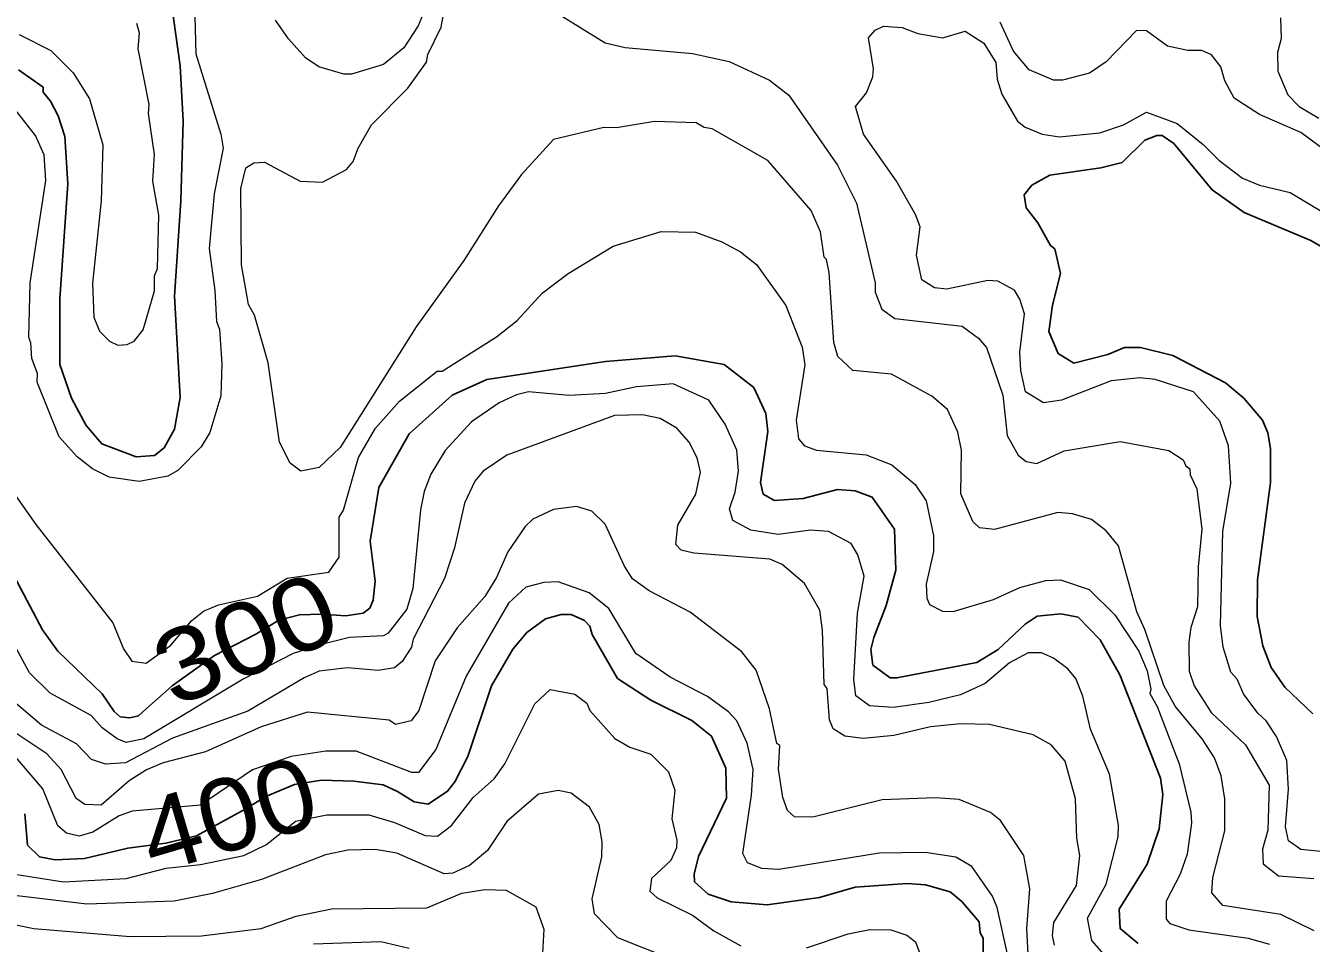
# Model space of a CAD drawing. Extents: x 673.3 to 698.5, y 6984.3 to 7012.3.
# Drawn here: x 691.219 to 692.636, y 6995.457 to 6996.468 of the extents above; entities that cross this region are included whole.
import ezdxf
from ezdxf.enums import TextEntityAlignment as Align

# ---------------------------------------------------------------- set-up
doc = ezdxf.new("R2010")
doc.units = 0
doc.header["$LTSCALE"] = 0.032
doc.layers.add('1', color=7, linetype='Continuous', lineweight=25)
doc.layers.add('2', color=7, linetype='Continuous', lineweight=13)
doc.layers.add('61', color=7, linetype='Continuous')

msp = doc.modelspace()

# ---------------------------------------------------------------- linework, layer by layer
at = {"layer": '1'}
for points in [[(691.2112, 6996.4198), (691.2385, 6996.4005), (691.2384, 6996.3951), (691.2467, 6996.3853), (691.2551, 6996.3689), (691.2625, 6996.3462), (691.2658, 6996.294), (691.2569, 6996.1674), (691.2569, 6996.095), (691.2697, 6996.0578), (691.2858, 6996.0277), (691.3031, 6996.0076), (691.3408, 6995.9932), (691.361, 6995.9947), (691.3718, 6996.0032), (691.3831, 6996.0237), (691.3895, 6996.0588), (691.3831, 6996.1705), (691.3903, 6996.2754), (691.3929, 6996.3632), (691.3895, 6996.4242), (691.3692, 6996.5689)], [(692.6373, 6995.7103), (692.6065, 6995.7395), (692.5912, 6995.7611), (692.5823, 6995.7852), (692.5757, 6995.8174), (692.5762, 6995.8579), (692.5907, 6995.965), (692.5907, 6996.0024), (692.5876, 6996.0197), (692.5818, 6996.0338), (692.5612, 6996.0578), (692.5409, 6996.0747), (692.483, 6996.1048), (692.4474, 6996.1137), (692.4296, 6996.1137), (692.4113, 6996.1062), (692.3741, 6996.0967), (692.3567, 6996.1071), (692.3465, 6996.1316), (692.3506, 6996.1604), (692.3594, 6996.1952), (692.353, 6996.2225), (692.3482, 6996.2261), (692.3344, 6996.2511), (692.3213, 6996.2677), (692.3191, 6996.2819), (692.3278, 6996.2928), (692.3475, 6996.3035), (692.4037, 6996.3116), (692.427, 6996.3177), (692.4521, 6996.3423), (692.4653, 6996.3474), (692.4713, 6996.3472), (692.4839, 6996.3386), (692.5262, 6996.2874), (692.5617, 6996.2626), (692.635, 6996.2316), (692.6694, 6996.2114)], [(692.4447, 6995.457), (692.4248, 6995.4736), (692.424, 6995.495), (692.4548, 6995.5445), (692.4681, 6995.5833), (692.4718, 6995.6213), (692.4693, 6995.6392), (692.4245, 6995.7532), (692.4028, 6995.7917), (692.3787, 6995.8165), (692.3595, 6995.8205), (692.3336, 6995.8176), (692.3202, 6995.8089), (692.2905, 6995.781), (692.2671, 6995.7667), (692.1791, 6995.7497), (692.1715, 6995.75), (692.1526, 6995.7638), (692.1503, 6995.7811), (692.1537, 6995.7943), (692.1673, 6995.8294), (692.1779, 6995.8685), (692.1764, 6995.9136), (692.1519, 6995.9489), (692.1331, 6995.9557), (692.1135, 6995.9573), (692.0758, 6995.9475), (692.0441, 6995.9453), (692.0317, 6995.9522), (692.0289, 6995.9649), (692.037, 6996.0213), (692.0345, 6996.0412), (692.0213, 6996.0699), (691.9888, 6996.0952), (691.9347, 6996.1047), (691.8581, 6996.0983), (691.7272, 6996.0785), (691.6891, 6996.0611), (691.6416, 6996.0186), (691.6084, 6995.9594), (691.5989, 6995.9003), (691.6044, 6995.8563), (691.6021, 6995.8354), (691.5984, 6995.8267), (691.591, 6995.821), (691.572, 6995.8181), (691.5451, 6995.8198), (691.521, 6995.8194), (691.4982, 6995.8133), (691.4728, 6995.7979), (691.4271, 6995.7746), (691.3808, 6995.7409), (691.3521, 6995.7155), (691.3434, 6995.708), (691.3339, 6995.7057), (691.3234, 6995.7068), (691.3167, 6995.7126), (691.3035, 6995.7323), (691.2547, 6995.7792), (691.2377, 6995.8027), (691.1783, 6995.9148)], [(691.2184, 6995.6001), (691.2213, 6995.5654), (691.2344, 6995.5525), (691.2516, 6995.5494), (691.2842, 6995.5509), (691.3317, 6995.5623), (691.3737, 6995.5675), (691.4076, 6995.5758), (691.4612, 6995.6051), (691.484, 6995.6192), (691.5154, 6995.6322), (691.5451, 6995.6371), (691.5809, 6995.636), (691.613, 6995.6318), (691.6287, 6995.6246), (691.6473, 6995.6132), (691.6628, 6995.6105), (691.684, 6995.6248), (691.692, 6995.6353), (691.7062, 6995.663), (691.7323, 6995.7412), (691.7558, 6995.7813), (691.7713, 6995.7999), (691.7919, 6995.8148), (691.809, 6995.8197), (691.8203, 6995.8197), (691.835, 6995.8131), (691.8407, 6995.8066), (691.8433, 6995.7974), (691.8714, 6995.7492), (691.9078, 6995.7251), (691.953, 6995.7028), (691.9748, 6995.6857), (691.9906, 6995.6503), (691.9914, 6995.6173), (691.9606, 6995.5529), (691.9556, 6995.5334), (691.956, 6995.5252), (691.9712, 6995.5114), (691.9966, 6995.5029), (692.0361, 6995.4997), (692.0937, 6995.5078), (692.1331, 6995.5192), (692.1903, 6995.5232), (692.2106, 6995.5217), (692.2376, 6995.5141), (692.2505, 6995.5035), (692.2697, 6995.4811), (692.2708, 6995.4687), (692.2739, 6995.463), (692.274, 6995.4431)]]:
    msp.add_lwpolyline(points, dxfattribs=at)
at = {"layer": '2'}
for points in [[(692.6387, 6995.4711), (692.602, 6995.4891), (692.5382, 6995.499), (692.526, 6995.5131), (692.5272, 6995.5298), (692.5402, 6995.5813), (692.5402, 6995.6164), (692.5362, 6995.6418), (692.5288, 6995.6617), (692.5152, 6995.6827), (692.4857, 6995.7187), (692.4729, 6995.7414), (692.4522, 6995.803), (692.4434, 6995.8224), (692.4232, 6995.8952), (692.4097, 6995.9119), (692.3933, 6995.9243), (692.3723, 6995.9305), (692.3563, 6995.932), (692.2865, 6995.9134), (692.2699, 6995.915), (692.2625, 6995.9219), (692.2496, 6995.9527), (692.2503, 6996.0005), (692.246, 6996.0206), (692.2347, 6996.0454), (692.2176, 6996.0601), (692.173, 6996.0843), (692.1305, 6996.0883), (692.1138, 6996.1039), (692.1095, 6996.1194), (692.1044, 6996.1965), (692.1014, 6996.2109), (692.0989, 6996.2133), (692.0949, 6996.2413), (692.0846, 6996.2649), (692.0367, 6996.3199), (691.9756, 6996.3547), (691.9667, 6996.3562), (691.9577, 6996.3612), (691.9119, 6996.3629), (691.8702, 6996.3558), (691.856, 6996.3563), (691.8007, 6996.3431), (691.7653, 6996.3045), (691.7401, 6996.2698), (691.7021, 6996.2095), (691.6493, 6996.1365), (691.5658, 6996.0037), (691.5424, 6995.9814), (691.5225, 6995.9777), (691.5106, 6995.9862), (691.4988, 6996.0096), (691.4864, 6996.0969), (691.4715, 6996.1493), (691.4649, 6996.1612), (691.4571, 6996.2047), (691.4564, 6996.2891), (691.4617, 6996.3117), (691.4707, 6996.3173), (691.4823, 6996.318), (691.5218, 6996.2972), (691.5464, 6996.2961), (691.5725, 6996.3098), (691.58, 6996.3188), (691.5855, 6996.3333), (691.6003, 6996.359), (691.6402, 6996.3996), (691.6607, 6996.4283), (691.6623, 6996.4367), (691.6771, 6996.4666), (691.6867, 6996.5211)], [(691.405, 6996.5073), (691.4067, 6996.4373), (691.4344, 6996.3488), (691.4367, 6996.3333), (691.4269, 6996.283), (691.4214, 6996.223), (691.4278, 6996.1767), (691.4295, 6996.1423), (691.4327, 6996.134), (691.4352, 6996.0959), (691.4343, 6996.0607), (691.4221, 6996.02), (691.4127, 6996.0042), (691.3869, 6995.9783)], [(691.6591, 6996.4858), (691.6518, 6996.4683), (691.6359, 6996.4439), (691.6135, 6996.4255), (691.5783, 6996.4151), (691.5696, 6996.415), (691.5423, 6996.423), (691.5274, 6996.4328), (691.5088, 6996.4538), (691.4946, 6996.4744)], [(691.7893, 6996.4918), (691.8578, 6996.4493), (691.8795, 6996.4445), (691.9537, 6996.4378), (691.9944, 6996.4289), (692.0386, 6996.4084), (692.0601, 6996.3918), (692.1137, 6996.3146), (692.1346, 6996.2728), (692.1549, 6996.1851), (692.1551, 6996.1747), (692.1624, 6996.1561), (692.1769, 6996.1457), (692.2509, 6996.1372), (692.269, 6996.1242), (692.2778, 6996.1139), (692.2958, 6996.0613), (692.3004, 6996.0168), (692.3127, 6995.9952), (692.3215, 6995.9882), (692.3333, 6995.986), (692.3633, 6995.9998), (692.4251, 6996.0102), (692.4784, 6996.0004), (692.4943, 6995.9902), (692.4973, 6995.9834), (692.5017, 6995.9802), (692.5021, 6995.9734), (692.5093, 6995.9581), (692.515, 6995.9135), (692.511, 6995.8721), (692.5101, 6995.8279), (692.5029, 6995.8053), (692.5007, 6995.7893), (692.5011, 6995.7572), (692.5063, 6995.741), (692.5253, 6995.7118), (692.5632, 6995.6761), (692.589, 6995.6317), (692.5875, 6995.5819), (692.5819, 6995.561), (692.5826, 6995.5449), (692.5992, 6995.5315), (692.6383, 6995.5289)], [(691.2121, 6996.4586), (691.2468, 6996.4412), (691.2716, 6996.4164), (691.2896, 6996.3876), (691.3041, 6996.337), (691.3024, 6996.2755), (691.2927, 6996.1848), (691.2942, 6996.1474), (691.3006, 6996.1319), (691.3116, 6996.1209), (691.3207, 6996.1162), (691.3312, 6996.1172), (691.3388, 6996.1209), (691.3488, 6996.1333), (691.361, 6996.1764), (691.3611, 6996.1927), (691.3643, 6996.2009), (691.3659, 6996.2597), (691.3595, 6996.2969), (691.361, 6996.3265), (691.3546, 6996.3716), (691.3553, 6996.3816), (691.3432, 6996.4429), (691.3447, 6996.4603), (691.3416, 6996.4707)], [(692.6646, 6995.5565), (692.6239, 6995.5606), (692.6103, 6995.5701), (692.607, 6995.5855), (692.6104, 6995.627), (692.6086, 6995.6589), (692.597, 6995.6853), (692.5859, 6995.7024), (692.5765, 6995.711), (692.561, 6995.7321), (692.5538, 6995.7484), (692.547, 6995.7562), (692.5386, 6995.7838), (692.5354, 6995.8074), (692.5379, 6995.9112), (692.5467, 6995.9644), (692.5443, 6996.0054), (692.5349, 6996.0325), (692.5059, 6996.0648), (692.4635, 6996.0787), (692.4468, 6996.0803), (692.4149, 6996.077), (692.3602, 6996.0556), (692.3405, 6996.0527), (692.3205, 6996.065), (692.3156, 6996.0885), (692.3146, 6996.1086), (692.3195, 6996.1508), (692.3145, 6996.1669), (692.3084, 6996.1769), (692.2902, 6996.187), (692.2791, 6996.1877), (692.2339, 6996.1781), (692.2205, 6996.1797), (692.2066, 6996.1885), (692.2006, 6996.2154), (692.2046, 6996.2466), (692.1994, 6996.2602), (692.1786, 6996.2969), (692.1422, 6996.3488), (692.1333, 6996.3792), (692.1455, 6996.3944), (692.1525, 6996.412), (692.1533, 6996.4209), (692.1479, 6996.4549), (692.155, 6996.4636), (692.1643, 6996.4679), (692.1849, 6996.4664), (692.2021, 6996.4596), (692.2296, 6996.455), (692.2542, 6996.4622), (692.2747, 6996.4491), (692.288, 6996.4277), (692.2895, 6996.4093), (692.2945, 6996.3928), (692.3118, 6996.363), (692.3202, 6996.3565), (692.3389, 6996.3489), (692.3581, 6996.3459), (692.4025, 6996.3504), (692.4285, 6996.3591), (692.4541, 6996.3732), (692.4876, 6996.3607), (692.5165, 6996.3376), (692.5335, 6996.3201), (692.5596, 6996.3003), (692.5783, 6996.2927), (692.6122, 6996.2845), (692.6638, 6996.2539)], [(692.3514, 6996.4085), (692.3246, 6996.4198), (692.3074, 6996.4402), (692.2928, 6996.4722)], [(692.6014, 6996.4771), (692.6022, 6996.4543), (692.5981, 6996.4389), (692.5988, 6996.4184), (692.6096, 6996.3922), (692.6222, 6996.3794), (692.6439, 6996.3665)], [(692.6888, 6996.3024), (692.624, 6996.3507), (692.5784, 6996.3707), (692.5505, 6996.3886), (692.5403, 6996.4077), (692.536, 6996.4232), (692.5255, 6996.4361), (692.515, 6996.441), (692.4996, 6996.4411), (692.4771, 6996.4459), (692.4541, 6996.4628), (692.4429, 6996.463), (692.4094, 6996.4284), (692.391, 6996.4161), (692.3614, 6996.4085), (692.3514, 6996.4085)], [(691.3869, 6995.9783), (691.3757, 6995.972), (691.3444, 6995.9662), (691.3111, 6995.971), (691.2929, 6995.98), (691.2761, 6995.9933), (691.2561, 6996.0153), (691.2319, 6996.0756), (691.2322, 6996.0851), (691.2259, 6996.1016), (691.2251, 6996.1188), (691.2226, 6996.1247), (691.2243, 6996.1851), (691.2413, 6996.2979), (691.2397, 6996.326), (691.2299, 6996.3474), (691.2036, 6996.3811)], [(691.171, 6996.0027), (691.2303, 6995.9187), (691.3154, 6995.8106), (691.327, 6995.7817), (691.3361, 6995.7682), (691.3521, 6995.766), (691.3793, 6995.7858), (691.4023, 6995.8129), (691.4153, 6995.8232), (691.4317, 6995.8304), (691.4745, 6995.8398), (691.5072, 6995.8595), (691.5534, 6995.8664), (691.5646, 6995.8827), (691.5647, 6995.9269), (691.5695, 6995.9346), (691.586, 6995.9926), (691.6047, 6996.0251), (691.6311, 6996.0547), (691.6724, 6996.0876), (691.6782, 6996.0879), (691.7378, 6996.1254), (691.7607, 6996.1437), (691.7883, 6996.1737), (691.8168, 6996.1955), (691.8666, 6996.2255), (691.9195, 6996.2415), (691.9572, 6996.2407), (691.986, 6996.2304), (692.0066, 6996.2191), (692.0243, 6996.2053), (692.0565, 6996.1601), (692.0745, 6996.1143), (692.0777, 6996.0947), (692.068, 6996.0336), (692.0707, 6996.0131), (692.0771, 6996.0054), (692.0905, 6996.0005), (692.1451, 6995.9954), (692.1733, 6995.9844), (692.1992, 6995.9628), (692.2114, 6995.9447), (692.2194, 6995.9063), (692.2194, 6995.8892), (692.2113, 6995.8529), (692.2119, 6995.8377), (692.2149, 6995.8308), (692.2292, 6995.8234), (692.2409, 6995.823), (692.2855, 6995.8363), (692.3145, 6995.8492), (692.3432, 6995.8571), (692.3594, 6995.8579), (692.3908, 6995.8471), (692.4191, 6995.8194), (692.4457, 6995.7793), (692.4546, 6995.7574), (692.4588, 6995.7375), (692.4576, 6995.7325), (692.4656, 6995.7181)], [(692.407, 6995.4455), (692.3938, 6995.4603), (692.3888, 6995.4849), (692.4097, 6995.5226), (692.4229, 6995.5748), (692.423, 6995.5874), (692.4132, 6995.6438), (692.3921, 6995.6933), (692.384, 6995.7298), (692.376, 6995.7491), (692.3674, 6995.7596), (692.3516, 6995.7715), (692.3383, 6995.7773), (692.3236, 6995.7773), (692.303, 6995.7665), (692.2761, 6995.7435), (692.249, 6995.731), (692.2143, 6995.7227), (692.1748, 6995.7171), (692.1488, 6995.7191), (692.1338, 6995.7301), (692.1314, 6995.748), (692.1355, 6995.821), (692.1428, 6995.8618), (692.1361, 6995.8852), (692.1286, 6995.898), (692.1036, 6995.9109), (692.084, 6995.9125), (692.0483, 6995.9078), (692.018, 6995.9124), (691.9981, 6995.9231), (691.9947, 6995.9359), (692.001, 6995.9543), (692.0044, 6995.9775), (692.0026, 6996.0008), (691.99, 6996.0293), (691.9718, 6996.0557), (691.9327, 6996.0737), (691.892, 6996.0705), (691.8581, 6996.0632), (691.8181, 6996.0608), (691.7731, 6996.0648), (691.7598, 6996.0616), (691.7408, 6996.0527), (691.7102, 6996.032), (691.6814, 6996.0002), (691.6655, 6995.9742), (691.6583, 6995.9552), (691.6542, 6995.935), (691.6459, 6995.8484), (691.6392, 6995.8256), (691.6187, 6995.7991), (691.6133, 6995.7961), (691.5759, 6995.7944), (691.5466, 6995.7871), (691.5141, 6995.7765), (691.4589, 6995.7483), (691.3494, 6995.6826), (691.3301, 6995.6787), (691.3199, 6995.6826), (691.3035, 6995.6946), (691.2914, 6995.7083), (691.2462, 6995.7331), (691.2234, 6995.7554), (691.2037, 6995.7922)], [(692.1418, 6995.6829), (692.1215, 6995.6855), (692.1087, 6995.6938), (692.1046, 6995.7034), (692.1021, 6995.7379), (692.0989, 6995.7426), (692.0972, 6995.8024), (692.094, 6995.8243), (692.0771, 6995.8537), (692.0527, 6995.8748), (692.0391, 6995.8807), (691.9553, 6995.8873), (691.9412, 6995.8905), (691.9355, 6995.8966), (691.9376, 6995.9179), (691.9574, 6995.9522), (691.9628, 6995.9765), (691.9588, 6995.9923), (691.95, 6996.0094), (691.9367, 6996.025), (691.9184, 6996.0354), (691.8988, 6996.0395), (691.8679, 6996.0387), (691.7493, 6995.995), (691.7231, 6995.9774), (691.7142, 6995.9665), (691.7025, 6995.9424), (691.6916, 6995.893), (691.6805, 6995.8594), (691.6463, 6995.7926), (691.6444, 6995.7838), (691.634, 6995.7679), (691.6256, 6995.7607), (691.6077, 6995.7578), (691.5738, 6995.761), (691.5427, 6995.7572), (691.5261, 6995.7499), (691.464, 6995.7131), (691.3809, 6995.6834), (691.3294, 6995.6562), (691.3071, 6995.6547), (691.2916, 6995.6598), (691.2753, 6995.6771), (691.2367, 6995.6977), (691.2046, 6995.7247)], [(692.0468, 6995.6774), (692.0386, 6995.7157), (692.0238, 6995.7581), (692.0082, 6995.7783), (691.9512, 6995.8223), (691.9062, 6995.8458), (691.8879, 6995.8589), (691.879, 6995.8727), (691.8578, 6995.919), (691.843, 6995.9333), (691.826, 6995.9386), (691.8008, 6995.9353), (691.7781, 6995.9248), (691.7696, 6995.9165), (691.7504, 6995.8888), (691.738, 6995.8602), (691.7252, 6995.8395), (691.6947, 6995.8048), (691.6703, 6995.7686), (691.6525, 6995.7139), (691.6438, 6995.7026), (691.6266, 6995.6984), (691.6197, 6995.7032), (691.5297, 6995.7121), (691.4786, 6995.6959), (691.4174, 6995.6682), (691.3709, 6995.6562), (691.3523, 6995.6483), (691.3332, 6995.6365), (691.3024, 6995.6097), (691.2846, 6995.6104), (691.2748, 6995.617), (691.2584, 6995.6487), (691.2426, 6995.6661), (691.1931, 6995.6993)], [(692.0302, 6995.5397), (692.0143, 6995.546), (692.0094, 6995.5562), (692.019, 6995.6204), (692.0206, 6995.6489), (692.0141, 6995.678), (692.0027, 6995.7023), (691.9936, 6995.7122), (691.9702, 6995.7292), (691.9293, 6995.7504), (691.8914, 6995.7766), (691.8618, 6995.8262), (691.8401, 6995.8435), (691.8057, 6995.8555), (691.79, 6995.8548), (691.7704, 6995.8498), (691.751, 6995.8321), (691.7045, 6995.7515), (691.671, 6995.6709), (691.6519, 6995.6457), (691.6445, 6995.6455), (691.5835, 6995.6691), (691.55, 6995.669), (691.5117, 6995.6633), (691.4691, 6995.6484), (691.412, 6995.6096), (691.3366, 6995.603), (691.3223, 6995.5979), (691.2934, 6995.5798), (691.2783, 6995.5754), (691.2644, 6995.5786), (691.2546, 6995.5868), (691.238, 6995.6275), (691.2019, 6995.6702)], [(691.1956, 6995.5355), (691.261, 6995.525), (691.3298, 6995.5286), (691.3741, 6995.5403), (691.412, 6995.5442), (691.4597, 6995.5539), (691.4846, 6995.5663), (691.5164, 6995.5918), (691.5509, 6995.5988), (691.5972, 6995.5989), (691.6256, 6995.5906), (691.6594, 6995.5761), (691.6729, 6995.5754), (691.6882, 6995.5873), (691.7124, 6995.618), (691.7352, 6995.6385), (691.747, 6995.6552), (691.7802, 6995.7212), (691.7971, 6995.737), (691.8242, 6995.7319), (691.8373, 6995.7219), (691.8409, 6995.7137), (691.8684, 6995.683), (691.8849, 6995.6734), (691.9081, 6995.6657), (691.9273, 6995.6464), (691.9345, 6995.626), (691.9312, 6995.5946), (691.9367, 6995.5711), (691.9362, 6995.5624), (691.93, 6995.5484), (691.9085, 6995.5289), (691.9067, 6995.5146), (691.9148, 6995.5075), (691.9539, 6995.4882), (691.9773, 6995.4709)], [(692.4656, 6995.7181), (692.4898, 6995.655), (692.5027, 6995.602), (692.5036, 6995.5898), (692.4987, 6995.5556), (692.4909, 6995.5336), (692.4756, 6995.5037), (692.4756, 6995.484), (692.4798, 6995.479), (692.5006, 6995.4721), (692.5661, 6995.463), (692.5894, 6995.4563)], [(692.3528, 6995.4554), (692.3506, 6995.466), (692.352, 6995.4802), (692.3769, 6995.521), (692.3806, 6995.554), (692.3774, 6995.5731), (692.3757, 6995.6164), (692.3644, 6995.6581), (692.3489, 6995.6761), (692.329, 6995.6871), (692.2811, 6995.6984), (692.2492, 6995.6991), (692.2161, 6995.6959), (692.1757, 6995.6862), (692.1418, 6995.6829)], [(692.3236, 6995.4454), (692.322, 6995.4737), (692.3253, 6995.5174), (692.3187, 6995.5542), (692.2932, 6995.5928), (692.2823, 6995.6013), (692.2477, 6995.6159), (692.2217, 6995.6178), (692.1627, 6995.6153), (692.0865, 6995.5963), (692.0663, 6995.5966), (692.0585, 6995.6037), (692.0532, 6995.6181), (692.0484, 6995.6493), (692.05, 6995.6752), (692.0468, 6995.6774)], [(691.8545, 6995.5692), (691.8512, 6995.5883), (691.8405, 6995.6072), (691.8202, 6995.6226), (691.8057, 6995.6258), (691.7843, 6995.6216), (691.7494, 6995.5914), (691.7281, 6995.5597), (691.7082, 6995.5429), (691.6898, 6995.5346), (691.6802, 6995.534), (691.6282, 6995.5566), (691.6043, 6995.5607), (691.5741, 6995.5598), (691.5494, 6995.5548), (691.479, 6995.5275), (691.4251, 6995.5123), (691.3828, 6995.5038), (691.2867, 6995.5005), (691.2008, 6995.5108)], [(691.9844, 6995.4184), (691.8716, 6995.4635), (691.8457, 6995.4899), (691.8432, 6995.5064), (691.8539, 6995.5526), (691.8545, 6995.5692)], [(692.3008, 6995.4454), (692.2895, 6995.4969), (692.2842, 6995.5093), (692.2617, 6995.542), (692.2439, 6995.5524), (692.2103, 6995.5574), (692.1593, 6995.5568), (692.0488, 6995.5388), (692.0302, 6995.5397)], [(691.4787, 6995.4736), (691.5174, 6995.4874), (691.5562, 6995.4955), (691.661, 6995.4965), (691.6998, 6995.5126), (691.7252, 6995.5167), (691.7484, 6995.5159), (691.7812, 6995.4977), (691.7902, 6995.473), (691.7886, 6995.4464)], [(691.1777, 6995.4839), (691.2284, 6995.4736), (691.3343, 6995.4647), (691.4129, 6995.4654), (691.4787, 6995.4736)], [(691.9773, 6995.4709), (692.007, 6995.4546)], [(692.0793, 6995.4524), (692.1252, 6995.4679), (692.1491, 6995.4727), (692.1723, 6995.4721), (692.1901, 6995.4662), (692.1996, 6995.459), (692.2088, 6995.4343)], [(691.6417, 6995.4515), (691.6106, 6995.4589), (691.5362, 6995.4564)]]:
    msp.add_lwpolyline(points, dxfattribs=at)

# ---------------------------------------------------------------- texts
at = {"layer": '61'}
for s, rotation, width, p in [('300', 22.714, 1.15, (691.4769, 6995.7562)), ('400', 16.504, 1.1, (691.4536, 6995.5611))]:
    msp.add_text(s, height=0.08, rotation=rotation, dxfattribs=dict(at, width=width)).set_placement(p, align=Align.CENTER)

doc.saveas('drawing.dxf')
